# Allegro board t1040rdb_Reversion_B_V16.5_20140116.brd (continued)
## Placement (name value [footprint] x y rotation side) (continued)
U26  PI3PCIE3212  [QFN_P050_D040_B450X250_20_E3X1]  234.7 97.54 0 top
U27  PI3PCIE3212  [QFN_P050_D040_B450X250_20_E3X1]  209.3 82.3 270 top
U28  PI3PCIE3212  [QFN_P050_D040_B450X250_20_E3X1]  234.7 106.43 0 top
U29  PI3PCIE3212  [QFN_P050_D040_B450X250_20_E3X1]  234.7 115.32 0 top
U37  MIC2506YM  [SO_8]  60.71 28.7 270 top
U38  VBUS054B-HSF  [TVS_LLP75_6L]  73.79 26.8 270 top
U39  MAX3232  [TSSOP_16]  136.14 66.42 90 top
U40  TXBN0304RSV  [QFN_P040_D040_B260X180_16]  171.2 92.46 270 top
U41  MAX3232  [TSSOP_16]  129.03 66.42 90 top
U42  TXBN0304RSV  [QFN_P040_D040_B260X180_16]  166.62 92.46 270 top
U43  LCDA15C-8  [SO_16]  131.19 33.4 0 top
U44  AT24C256  [SO_8]  236.47 150.5 0 top
U45  ADT7461  [MSOP_8]  144.91 120.52 180 bottom
U46  RTL8211E-VB  [QFN_P040_D040_B600_48_E440]  158.5 49.91 90 top
U47  SRV05-4  [SOT23_6]  155.96 42.29 270 top
U48  SRV05-4  [SOT23_6]  162.05 42.29 270 top
U49  RTL8211E-VB  [QFN_P040_D040_B600_48_E440]  136.27 50.55 90 top
U50  SRV05-4  [SOT23_6]  139.57 42.29 270 top
U51  SRV05-4  [SOT23_6]  145.54 42.29 270 top
U52  RTL8211DN  [QFN_P040_D040_B1000_88_E600]  191.52 65.15 90 top
U53  SRV05-4  [SOT23_6]  190.12 30.23 270 top
U54  SRV05-4  [SOT23_6]  196.09 30.23 270 top
U55  F104S8A  [QFN_VSC8514]  212.47 65.15 180 top
U56  F104S8A  [QFN_VSC8514]  246.76 65.15 180 top
U57  CS4315  [BGA_P100_121]  169.29 65.15 0 top
U58  AT24C64  [TSSOP_8]  159.77 62.99 90 top
U59  Le88266DLC  [QFP_P065_80_E780]  86.74 56.9 180 top
U60  TISP61089B  [SO_8]  93.6 41.78 270 top
U61  TISP61089B  [SO_8]  84.71 41.78 270 top
U62  TISP61089B  [SO_8]  111.38 41.78 270 top
U63  Le88266DLC  [QFP_P065_80_E780]  109.6 56.9 180 top
U64  TISP61089B  [SO_8]  102.49 41.78 270 top
U65  EPM570GF256  [BGA_P100_256]  64.52 106.43 0 top
U67  ICS843002-01  [TSSOP_20]  231.27 72.39 0 top
U68  ICS843002-01  [TSSOP_20]  152.27 67.18 0 top
U69  IR3550  [QFN_IR3550]  107.82 94.23 90 top
U70  IR36021  [QFN_P050_D040_B500_32_E345]  100.71 83.57 90 bottom
U71  IR3550  [QFN_IR3550]  107.82 104.39 90 top
U72  MIC39102YM  [SO_8]  93.22 82.3 0 top
U81  TPS51200  [DFN_P050_D040_B300_10_E240X165]  227.33 146.69 270 top
U82  NCP571  [SOT23_5]  72.64 151.13 180 top
U83  MIC811  [SOT143]  19.05 65.41 180 top
U84  74LVC2G74  [U8]  11.18 64.01 180 top
U85  74AHC1G14  [SC70_5]  12.32 61.21 90 top
U86  IR3473  [QFN_SUPIRBUCK_4X5]  197.23 79.76 90 top
U87  IR3475  [QFN_SUPIRBUCK_4X5]  217.55 136.91 90 top
U88  IR3473  [QFN_SUPIRBUCK_4X5]  23.88 112.14 270 top
U89  IR3473  [QFN_SUPIRBUCK_4X5]  23.88 101.35 270 top
U90  IR3475  [QFN_SUPIRBUCK_4X5]  23.88 90.55 270 top
U91  IR3473  [QFN_SUPIRBUCK_4X5]  61.34 80.39 270 top
U92  ADG836  [MSOP_10]  107.19 78.61 180 bottom
U93  RClamp0524J.TCT  [TVS_SLP2710P8]  44.45 37.34 180 bottom
U94  RClamp0524J.TCT  [TVS_SLP2710P8]  30.73 37.34 180 bottom
U95  MIC47100YMME  [MSOP_8_E170]  207.9 125.98 180 top
U96  VBUS054B-HSF  [TVS_LLP75_6L]  76.33 26.8 270 top
U97  IDT9FGV0641  [QFN_P040_D040_B500_40_E370]  236.6 136.91 90 top
U98  TXBN0304RSV  [QFN_P040_D040_B260X180_16]  81.41 130.68 180 bottom
U99  TXBN0304RSV  [QFN_P040_D040_B260X180_16]  81.41 124.59 180 bottom
U100  74LVC1G32  [SC70_5]  272.42 140.72 0 top
U101  74LVC1G32  [SC70_5]  275.21 140.72 0 top
X1  24MHz,+/-50ppm  [OSC_7X5_4]  84.84 89.28 0 top
X2  32.768KHz  [OSC_32X25_4]  51.69 111.38 0 top
X3  100MHz,+/-50ppm  [OSC_7X5_4]  84.84 97.54 0 top
X5  66.66MHz,+/-50ppm  [OSC_7X5_4]  84.84 105.79 0 top
Y1  25MHz  [CRY_32X25_4]  150.5 50.8 270 top
Y2  25MHz  [CRY_32X25_4]  128.27 51.43 270 top
Y3  25MHz  [CRY_32X25_4]  182.25 62.74 270 top
Y4  25MHz  [CRY_32X25_4]  235.46 130.17 0 top
Y5  25MHz  [CRY_32X25_4]  155.07 60.45 0 top
Y6  25MHz  [CRY_32X25_4]  232.28 65.53 0 top
Z97  -  [FIDUCIAL]  274.7 18.16 0 top
Z98  -  [FIDUCIAL]  11.81 239.14 0 top
Z99  -  [FIDUCIAL]  10.54 22.61 0 top
Z100  -  [FIDUCIAL]  268.99 240.41 0 top
Z101  -  [FIDUCIAL]  274.7 18.16 180 bottom
Z102  -  [FIDUCIAL]  11.81 239.14 180 bottom
Z103  -  [FIDUCIAL]  268.99 240.41 180 bottom
Z104  -  [FIDUCIAL]  10.54 22.61 180 bottom
Z105  MH_M8  [MH_900C400N_M]  141.02 245.02 0 top
Z106  MH_M8  [MH_900C400N_M]  275.02 245.02 0 top
Z107  MH_M8  [MH_900C400N_M]  127.02 11.02 0 top
Z108  MH_M8  [MH_900C400N_M]  275.02 11.02 0 top
Z109  MH_M8  [MH_900C400N_M]  7.02 16.02 0 top
Z110  MH_M8  [MH_900C400N_M]  7.02 245.02 0 top
Z111  MH_M8  [MH_900C400N_M]  34.04 133.73 0 top
Z112  MH_M8  [MH_900C400N_M]  220.73 84.84 0 top

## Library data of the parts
C1 C2 C15 C375 C391 C576 C578 C580 C583 C592 C596 C755 C758 C773 C774 C781-C784 C787-C794 C885 C886 C925 C926 C930 C931 C952-C955 C975 C976 C979 C980 = CAP: signal model: DEFAULT_CAPACITOR_2.2e+07pF_2_1
C3-C14 C16-C21 C23-C26 C28-C32 C34 C35 C37 C39-C43 C48-C54 C57-C68 C84 C93 C94 C131 C133 C136 C147 C148 C150-C159 C170 C171 C176 C177 C179 C180 C182-C185 C192 C196-C208 C210-C220 C222 C232 C245-C248 C252-C256 C271-C275 C280-C288 C293 C295 C297 C306 C313-C317 C319-C323 C325 C326 C329 C336 C344 C346-C351 C353-C355 C357 C358 C361 C366-C368 C376-C378 C381-C386 C388-C390 C392 C393 C398-C400 C403-C407 C410 C411 C414-C416 C423-C425 C435-C437 C445 C448-C451 C454-C456 C459 C461 C462 C468-C470 C480-C482 C490-C497 C504-C511 C518-C525 C532-C539 C549 C554 C555 C564 C565 C572-C575 C586 C590 C593 C594 C597-C599 C602-C608 C611-C619 C622-C625 C627-C631 C636 C645 C649-C651 C653-C658 C669 C673-C675 C677-C681 C685 C686 C688 C694 C695 C699-C701 C704 C706-C710 C712-C716 C720 C723 C729 C732 C735 C742-C749 C762 C883 C891 C893-C898 C916-C919 C933 C935 C940 C941 C961 C963-C965 C984 C987-C989 C997-C1002 C1011 C1012 C1018-C1022 C1025-C1036 C1044-C1048 C1050-C1052 C1059-C1062 C1071-C1074 C1076 C1079 C1081-C1087 = CAP: signal model: DEFAULT_CAPACITOR_100000pF_2_1
C22 C69-C83 C85 C134 C139 C163-C169 C223-C230 C296 C298 C299 C301 C310 C328 C330 C332 C333 C342 C360 C362-C364 C371 C544 C545 C548 C550 C552 C553 C591 C595 C632-C635 C702 C721 C730 C737 C751 C753 C761 C770 C871 C873-C876 C878 C879 C920-C923 C932 C938 C945 C947 C956 C957 C969 C971 C977 C981 C993 C995 C996 C1003-C1010 C1023 C1024 C1037-C1039 C1041 C1078 = CAP: signal model: DEFAULT_CAPACITOR_10000pF_2_1
C27 C33 C36 C38 C135 C238-C241 C258 C263 C268 C270 C402 C413 C422 C434 C440 C447 C458 C467 C479 C485 C558-C563 C568-C571 C577 C579 C581 C582 C584 C585 C587-C589 C693 C698 C703 C705 C711 C722 C731 C760 C796 C884 C899-C903 C912-C915 C928 C929 C944 C946 C950 C951 C968 C970 C972-C974 C978 C992 C994 C1015 C1016 C1053-C1058 C1088-C1094 = CAP: signal model: DEFAULT_CAPACITOR_1e+06pF_2_1
C55 C56 C132 C300 C303 C331 C335 C718 C728 = CAP: signal model: DEFAULT_CAPACITOR_10.000000pF_2_1
C92 C125 C128 C130 C137 C140-C146 C175 C178 C181 C186-C189 C195 C209 C234-C237 C257 C262 C267 C269 C401 C412 C420 C421 C432 C433 C446 C457 C465 C466 C477 C478 C556 C557 C566 C567 C600 C601 C609 C610 C621 C626 C646 C670 C736 C750 C752 C754 C757 C771 C772 C797 C880 C881 C888-C890 C904-C911 C1017 C1040 C1049 C1075 C1077 = CAP: signal model: DEFAULT_CAPACITOR_1e+07pF_2_1
C124 C127 C620 C689 = CAP_E: signal model: DEFAULT_CAPACITOR_1e+08pF_2_1
C126 C129 C294 C302 C309 C334 C341 C365 C374 C498 C499 C512 C513 C526 C527 C541 C542 C690 C766 C786 C887 = CAP: signal model: DEFAULT_CAPACITOR_1000pF_2_1
C138 C149 C161 C162 C173 C174 C242 C243 C249 C250 C798 = CAP: signal model: DEFAULT_CAPACITOR_2.2e+06pF_2_1
C160 C172 C244 C251 C259 C264 C764 = CAP: signal model: DEFAULT_CAPACITOR_3000pF_2_1
C260 C265 C312 C324 C343 C356 C551 C647 C648 C652 C671 C672 C676 C795 C882 = CAP: signal model: DEFAULT_CAPACITOR_4.7e+06pF_2_1
C261 C266 C934 C936 C937 C939 C958-C960 C962 C982 C983 C985 C986 C1063 C1064 C1066-C1070 C1095-C1100 = CAP: signal model: DEFAULT_CAPACITOR_4.7e+07pF_2_1
C276-C279 C289-C292 C778 = CAP: signal model: DEFAULT_CAPACITOR_100.000000pF_2_1
C304 C305 C339 C340 C372 C373 C739 C740 = CAP: signal model: DEFAULT_CAPACITOR_27.000000pF_2_1
C307 C308 C337 C338 C369 C370 C500-C503 C514-C517 C528-C531 C540 C543 C546 C547 C696 = CAP: signal model: DEFAULT_CAPACITOR_470.000000pF_2_1
C637 C638 C642 C644 C659 C660 C666 C668 = CAP: signal model: DEFAULT_CAPACITOR_68000pF_2_1
C639-C641 C643 C661 C662 C664 C667 = CAP: signal model: DEFAULT_CAPACITOR_22000pF_2_1
C682 = CAP: signal model: DEFAULT_CAPACITOR_4700pF_2_1
C683 = CAP: signal model: DEFAULT_CAPACITOR_4.700000pF_2_1
C684 = CAP: signal model: DEFAULT_CAPACITOR_330.000000pF_2_1
C687 C767 C768 C776 C777 = CAP_E: signal model: DEFAULT_CAPACITOR_4.7e+08pF_2_1
C691 C692 = CAP_E: signal model: DEFAULT_CAPACITOR_8.2e+07pF_2_1
C697 = CAP: signal model: DEFAULT_CAPACITOR_220.000000pF_2_1
C733 C734 = CAP: signal model: DEFAULT_CAPACITOR_2.000000pF_2_1
C738 C741 = CAP: signal model: DEFAULT_CAPACITOR_33.000000pF_2_1
C756 C763 C765 C769 C779 C785 = CAP: signal model: DEFAULT_CAPACITOR_220000pF_2_1
C759 C775 C1080 = CAP_E: signal model: DEFAULT_CAPACITOR_2.2e+08pF_2_1
C892 = CAP: signal model: DEFAULT_CAPACITOR_22.000000pF_2_1
C924 = CAP: signal model: DEFAULT_CAPACITOR_330000pF_2_1
C927 C948 C949 = CAP: signal model: DEFAULT_CAPACITOR_470000pF_2_1
C942 = CAP: signal model: DEFAULT_CAPACITOR_510.000000pF_2_1
C943 C966 = CAP: signal model: DEFAULT_CAPACITOR_560.000000pF_2_1
C967 = CAP: signal model: DEFAULT_CAPACITOR_620.000000pF_2_1
C990 C991 = CAP: signal model: DEFAULT_CAPACITOR_680.000000pF_2_1
C1013 C1014 = CAP_3T_4P
C1101-C1113 = CAP
D1 D5 D6 D36-D44 = LED
D3 D4 D25 D26 D28 = DIODE
D22 D30 D31 D33-D35 = DIODE_SCHOTTKY
D27 = DIODE_DUAL_A
F1-F13 = PTC
FB6-FB13 FB18-FB26 FB29 FB32 FB35-FB48 FB50 FB52-FB55 = BEAD
J1 = DDR3_DIMM
J2 = SD_CONN
J3 = CONN_2X8
J9-J11 J27 = JMP2
J13 = RJ45_2X1
J14 = RJ45_LED_2X1
J15 = RJ45_LED_8
J16 = SFP+_CONN
J17 = SFP_CAGE
J18 = PCIE_X4
J19 J20 = MINIPCIE_CONN
J21 = SATA_CONN
J22 J23 = RJ11_6P_2
J24 = RJ11_4P
J25 = TQ2-3V
J26 = CONN_2X5
J28 J32 = CONN_1X3
J30 = BAT_SOCKET
J31 J35 J39 = CONN_1X2
J33 J34 J44-J46 = CONN_3PIN
J37 = ATX_PWR_CONN_20PIN
J41 = USB_A_2
J42 = RJ45_LED
J43 = CONN_2X20
L1 L2 = IND_CM
L3 L4 L17 L18 L22 = IND_IRON: signal model: DEFAULT_INDUCTOR_2200nH_2_1
L5 L21 = IND_IRON: signal model: DEFAULT_INDUCTOR_4700nH_2_1
L6 = IND_IRON: signal model: DEFAULT_INDUCTOR_220000nH_2_1
L7 = IND_IRON: signal model: DEFAULT_INDUCTOR_100000nH_2_1
L8 L9 = IND_IRON: signal model: DEFAULT_INDUCTOR_215.000000nH_2_1
L16 = IND_IRON: signal model: DEFAULT_INDUCTOR_22000nH_2_1
L19 L20 = IND_IRON: signal model: DEFAULT_INDUCTOR_3300nH_2_1
L23 = IND_IRON: signal model: DEFAULT_INDUCTOR_1000nH_2_1
M2 = HEATSINK_FAN
M3-M18 = MH
Q1-Q4 Q6 Q7 Q13 Q15 Q16 Q20 Q21 Q25-Q29 Q32-Q41 Q44 Q45 = NMOS
Q5 = TRANS_PNP
Q8 Q9 Q11 Q17 Q18 Q23 Q24 Q31 Q42 Q43 = NMOS_SO8FL
Q12 = PMOS_SO8
Q30 = TRANS_NPN
R1 R3 = RES: tolerance: 1%; signal model: DEFAULT_RESISTOR_162.000000OHM_2_1
R2 R48 R83 R84 R138 R161 R162 R174 R176 R302 R323 R488 R494 R503 R505 R507 R509 R513 R516 R518 R533 R540 R560 R568 R654 R656 R665 R666 R670 R672 R673 R681 R682 R687 R692 R713 R782 R785 R815 R820 R829 R830 R834 R842-R844 R860 = RES: tolerance: 5%; signal model: DEFAULT_RESISTOR_1000.000000OHM_2_1
R4-R7 R9-R11 R13 R17 R19 R21 R23 R25 R27 R29 R31 R33-R47 R54-R57 R69-R82 R85-R99 R101 R102 R123 R124 R132 R135-R137 R141-R143 R185 R204 R228-R235 R252 R257-R264 R268-R270 R272 R273 R276-R279 R282 R293-R297 R314-R317 R320 R379-R385 R387-R393 R396-R411 R420 R428 R442 R496 R499-R501 R563 R569 R570 R573 R574 R705 R706 R708 R710 R712 R808-R813 R823 R845-R859 = RES: tolerance: 5%; signal model: DEFAULT_RESISTOR_4700OHM_2_1
R12 R59 R100 R108 R115-R122 R125-R130 R468 R486 R490 R549 R550 R553 R555 R694 R839 R841 = RES: tolerance: 5%; signal model: DEFAULT_RESISTOR_10.000000OHM_2_1
R14-R16 R18 R20 R22 R24 R26 R28 R30 R32 R58 R175 R209 R211 R213-R217 R238 R239 R242-R246 R419 R422 R448 R449 R495 R511 R517 = RES: tolerance: 5%; signal model: DEFAULT_RESISTOR_33.000000OHM_2_1
R49-R52 R61 R157 R160 R167-R170 R180 R182-R184 R190 R193 R221 R222 R250 R251 R281 R291 R312 R489 R520 R521 R525 R526 R530 R532 R536 R537 R552 R554 R559 R561 R579 R588 R589 R657 R659 R675 R676 R688 R689 R700 R701 R727 R742 R743 R760 R761 R778 R779 R783 R816 R817 R822 R824-R828 R836 R837 = RES: tolerance: 5%; signal model: DEFAULT_RESISTOR_0.001OHM_2_1
R60 R62-R68 R106 R107 R109-R114 R155 R156 R158 R159 R497 R498 R502 R504 R506 R508 R558 R564 R593 R660 R662 R663 R667 R669 R671 R678 R679 R684 R685 R690 R691 R693 R703 R704 R726 R732 R734 R737 R739-R741 R750 R752 R754 R756 R758 R759 R768 R770 R771 R773 R776 R777 R784 R786 R818 R819 R821 R831 = RES: tolerance: 5%; signal model: DEFAULT_RESISTOR_10000OHM_2_1
R103 R133 R186 R187 R218 R219 R247 R248 R274 R275 R339-R342 R351-R354 R363-R366 R375-R378 R394 R395 R439 R440 R470-R472 R699 R702 = RES: tolerance: 5%; signal model: DEFAULT_RESISTOR_510.000000OHM_2_1
R104 R105 R140 = RES: tolerance: 1%; signal model: DEFAULT_RESISTOR_698.000000OHM_2_1
R131 = RES: tolerance: 5%; signal model: DEFAULT_RESISTOR_1500OHM_2_1
R134 = RES: tolerance: 5%; signal model: DEFAULT_RESISTOR_270.000000OHM_2_1
R139 = RES: tolerance: 1%; signal model: DEFAULT_RESISTOR_200.000000OHM_2_1
R163 R164 = RES: tolerance: 1%; signal model: DEFAULT_RESISTOR_51100OHM_2_1
R165 R166 = RES: tolerance: 1%; signal model: DEFAULT_RESISTOR_18200OHM_2_1
R171 R599 R729 R731 R736 R738 R744 R748 R749 R753 R757 R766 R767 R772 R774 R807 = RES: tolerance: 1%; signal model: DEFAULT_RESISTOR_10000OHM_2_1
R172 R173 R519 R523 R524 R527 R528 R534 R535 R538 R814 R835 R838 = RES: tolerance: 1%; signal model: DEFAULT_RESISTOR_49.900000OHM_2_1
R177-R179 = RES: tolerance: 5%; signal model: DEFAULT_RESISTOR_330.000000OHM_2_1
R188 R191 R194 R195 = RES: tolerance: 5%; signal model: DEFAULT_RESISTOR_5.100000OHM_2_1
R189 R192 = RES: tolerance: 1%; signal model: DEFAULT_RESISTOR_0.33OHM_2_1
R196-R203 R205 R206 R220 R249 R280 R292 R313 R386 R426 R455 R551 R556 R707 R711 = RES: tolerance: 5%; signal model: DEFAULT_RESISTOR_100.000000OHM_2_1
R207 R208 R210 R212 R236 R237 R240 R241 R265-R267 R271 R331-R338 R343-R350 R355-R362 R367-R374 R595 = RES: tolerance: 5%; signal model: DEFAULT_RESISTOR_75.000000OHM_2_1
R224 R284 = RES: tolerance: 5%; signal model: DEFAULT_RESISTOR_15.000000OHM_2_1
R227 R256 R285 R780 = RES: tolerance: 1%; signal model: DEFAULT_RESISTOR_2490OHM_2_1
R253 = RES: signal model: DEFAULT_RESISTOR_15.000000OHM_2_1
R286 = RES: tolerance: 1%; signal model: DEFAULT_RESISTOR_12100OHM_2_1
R303 R324 = RES: tolerance: 1%; signal model: DEFAULT_RESISTOR_2000OHM_2_1
R412 R413 R434 R435 R441 R451 R464 R465 R480 R481 R716-R723 = RES: tolerance: 5%; signal model: DEFAULT_RESISTOR_200000OHM_2_1
R414 R416 R429 R431 R444 R452 R459 R461 = RES: tolerance: 1%; signal model: DEFAULT_RESISTOR_3010OHM_2_1
R417 R418 R421 R423 R425 R445-R447 R450 R453 = RES: tolerance: 5%; signal model: DEFAULT_RESISTOR_51.000000OHM_2_1
R430 R433 R460 R463 R473-R479 = RES: tolerance: 1%; signal model: DEFAULT_RESISTOR_402000OHM_2_1
R436 R437 R466 R467 = RES: tolerance: 1%; signal model: DEFAULT_RESISTOR_47500OHM_2_1
R438 R469 = RES: tolerance: 1%; signal model: DEFAULT_RESISTOR_75000OHM_2_1
R482-R485 = RES: tolerance: 5%; signal model: DEFAULT_RESISTOR_1800OHM_2_1
R487 R493 R557 = RES: tolerance: 5%; signal model: DEFAULT_RESISTOR_13000OHM_2_1
R491 = RES: tolerance: 2%; signal model: DEFAULT_RESISTOR_0.02OHM_2_1
R541-R548 = RES: tolerance: 5%; signal model: DEFAULT_RESISTOR_150.000000OHM_2_1
R562 R586 = RES: tolerance: 1%; signal model: DEFAULT_RESISTOR_3570OHM_2_1
R565 R566 R581 R582 R590 R591 = RES: tolerance: 1%; signal model: DEFAULT_RESISTOR_301.000000OHM_2_1
R567 R592 = RES: tolerance: 5%; signal model: DEFAULT_RESISTOR_1.000000OHM_2_1
R575 R781 = RES: tolerance: 1%; signal model: DEFAULT_RESISTOR_1780OHM_2_1
R576 R580 = RES: tolerance: 1%; signal model: DEFAULT_RESISTOR_2870OHM_2_1
R577 = RES_NTC: signal model: DEFAULT_RESISTOR_10000OHM_2_1
R578 = RES: tolerance: 1%; signal model: DEFAULT_RESISTOR_3400OHM_2_1
R594 = RES: tolerance: 1%; signal model: DEFAULT_RESISTOR_7500OHM_2_1
R596 = RES: tolerance: 1%; signal model: DEFAULT_RESISTOR_20000OHM_2_1
R597 = RES: tolerance: 1%; signal model: DEFAULT_RESISTOR_49900OHM_2_1
R598 = RES: tolerance: 1%; signal model: DEFAULT_RESISTOR_46400OHM_2_1
R695 R696 = RES: tolerance: 1%; signal model: DEFAULT_RESISTOR_1000.000000OHM_2_1
R697 R714 R715 = RES: tolerance: 5%; signal model: DEFAULT_RESISTOR_100000OHM_2_1
R709 = RES: tolerance: 1%; signal model: DEFAULT_RESISTOR_3740OHM_2_1
R724 R725 = RES: tolerance: 1%; signal model: DEFAULT_RESISTOR_619.000000OHM_2_1
R728 = RES: tolerance: 1%; signal model: DEFAULT_RESISTOR_169000OHM_2_1
R730 = RES: tolerance: 1%; signal model: DEFAULT_RESISTOR_124000OHM_2_1
R733 = RES: tolerance: 1%; signal model: DEFAULT_RESISTOR_1650OHM_2_1
R735 = RES: tolerance: 1%; signal model: DEFAULT_RESISTOR_2050OHM_2_1
R745 = RES: tolerance: 1%; signal model: DEFAULT_RESISTOR_5900OHM_2_1
R746 = RES: tolerance: 1%; signal model: DEFAULT_RESISTOR_187000OHM_2_1
R747 = RES: tolerance: 1%; signal model: DEFAULT_RESISTOR_226000OHM_2_1
R751 = RES: tolerance: 1%; signal model: DEFAULT_RESISTOR_2210OHM_2_1
R755 = RES: tolerance: 1%; signal model: DEFAULT_RESISTOR_2430OHM_2_1
R762 = RES: tolerance: 1%; signal model: DEFAULT_RESISTOR_4990OHM_2_1
R763 = RES: tolerance: 1%; signal model: DEFAULT_RESISTOR_3830OHM_2_1
R764 = RES: tolerance: 1%; signal model: DEFAULT_RESISTOR_309000OHM_2_1
R765 = RES: tolerance: 1%; signal model: DEFAULT_RESISTOR_412000OHM_2_1
R769 = RES: tolerance: 1%; signal model: DEFAULT_RESISTOR_2550OHM_2_1
R775 = RES: tolerance: 1%; signal model: DEFAULT_RESISTOR_2320OHM_2_1
R787 = RES: tolerance: 1%; signal model: DEFAULT_RESISTOR_32400OHM_2_1
R797-R804 = RES: tolerance: 5%; signal model: DEFAULT_RESISTOR_20000OHM_2_1
R806 = RES: tolerance: 1%; signal model: DEFAULT_RESISTOR_4320OHM_2_1
R861-R870 = RES: tolerance: 5%
SW1-SW3 = SWITCH_DIP_8
SW4 SW5 = SWITCH_2P2
T1-T3 = H5004
T4-T11 = GST5009LF
T12 = XFMR_POTS_10PIN
TP1-TP14 = TP
U1 = T1040
U2 = 74LVC16373
U4 = FLASH-NOR-64Mx16
U6 = FLASH-NAND-2
U7 U11 U12 U18 U20 U40 U42 U98 U99 = TXBN0304RSV
U8-U10 = 74LVC1G86
U13 = FLASH-SERIAL-SO16
U15 = FLASH-SERIAL-SON
U19 = PCA9546A
U21 U22 = FXLP34P5X
U23 U24 = 74LVC1G66
U25-U29 = PI3PCIE3212
U37 = MIC2506
U38 U47 U48 U50 U51 U53 U54 U96 = SRV05-4
U39 U41 = MAX3232
U43 = LCDA15C-8
U44 U58 = EEPROM-I2C
U45 = ADT7461
U46 U49 = RTL8211E-VB
U52 = RTL8211DN
U55 U56 = VSC8514
U57 = CS4315
U59 U63 = Le88266DLC
U60-U62 U64 = TISP61089
U65 = EPM570F256
U67 U68 = ICS843002-01
U69 U71 = IR3550
U70 = IR36021
U72 = MIC39102-SOIC
U81 = TPS51200
U82 = NCP571
U83 = MAX811S
U84 = 74LVC2G74
U85 = 74LVC1G14
U86-U91 = IR3475
U92 = ADG836
U93 U94 = RClamp0524J
U95 = MIC47100-MSOP8
U97 = IDT9FGV0641
U100 U101 = 74LVC1G32
X1-X3 X5 = OSC
Y1-Y6 = CRYSTAL_4PIN
Z97-Z104 = FIDUCIAL
Z105-Z112 = MH_M8

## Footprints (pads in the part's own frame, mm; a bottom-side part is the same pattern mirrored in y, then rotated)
0201
  rect 0.35x0.35 smd: 1(-0.3,0) 2(0.3,0)
0402
  rect 0.55x0.55 smd: 1(-0.5,0) 2(0.5,0)
0402O
  custom 0.138x0.138 smd: 1(-0.5,0) 2(0.5,0)
0603
  rect 0.9x0.9 smd: 1(-0.8,0) 2(0.8,0)
0805
  rect 1x1.4 smd: 1(-1,0) 2(1,0)
1206
  rect 1.25x1.6 smd: 1(-1.5,0) 2(1.5,0)
1210
  rect 1.4x2.6 smd: 1(-1.6,0) 2(1.6,0)
7343
  rect 2.4x2.9 smd: 1(-3.05,0) 2(3.05,0)
BGA_P080_780
  round 0.35 smd: A2(-10,10.8) A3(-9.2,10.8) A4(-8.4,10.8) A5(-7.6,10.8) A6(-6.8,10.8) A7(-6,10.8) A8(-5.2,10.8) A9(-4.4,10.8) A10(-3.6,10.8) A11(-2.8,10.8) A12(-2,10.8) A13(-1.2,10.8) A14(-0.4,10.8) A15(0.4,10.8) A16(1.2,10.8) A17(2,10.8) A18(2.8,10.8) A19(3.6,10.8) A20(4.4,10.8) A21(5.2,10.8) A22(6,10.8) A23(6.8,10.8) A24(7.6,10.8) A25(8.4,10.8) A26(9.2,10.8) A27(10,10.8) AA1(-10.8,-5.2) AA2(-10,-5.2) AA3(-9.2,-5.2) AA4(-8.4,-5.2) AA5(-7.6,-5.2) AA6(-6.8,-5.2) AA7(-6,-5.2) AA8(-5.2,-5.2) AA9(-4.4,-5.2) AA10(-3.6,-5.2) AA11(-2.8,-5.2) AA12(-2,-5.2) AA13(-1.2,-5.2) AA14(-0.4,-5.2) AA15(0.4,-5.2) AA16(1.2,-5.2) AA17(2,-5.2) AA18(2.8,-5.2) AA19(3.6,-5.2) AA20(4.4,-5.2) AA21(5.2,-5.2) AA22(6,-5.2) AA23(6.8,-5.2) AA24(7.6,-5.2) AA25(8.4,-5.2) AA26(9.2,-5.2) AA27(10,-5.2) AA28(10.8,-5.2) AB1(-10.8,-6) AB2(-10,-6) AB3(-9.2,-6) AB4(-8.4,-6) AB5(-7.6,-6) AB6(-6.8,-6) AB7(-6,-6) AB8(-5.2,-6) AB9(-4.4,-6) AB10(-3.6,-6) AB11(-2.8,-6) AB12(-2,-6) AB13(-1.2,-6) AB14(-0.4,-6) AB15(0.4,-6) AB16(1.2,-6) AB17(2,-6) AB18(2.8,-6) AB19(3.6,-6) AB20(4.4,-6) AB21(5.2,-6) AB22(6,-6) AB23(6.8,-6) AB24(7.6,-6) AB25(8.4,-6) AB26(9.2,-6) AB27(10,-6) AB28(10.8,-6) AC1(-10.8,-6.8) AC2(-10,-6.8) AC3(-9.2,-6.8) AC4(-8.4,-6.8) AC5(-7.6,-6.8) AC6(-6.8,-6.8) AC7(-6,-6.8) AC8(-5.2,-6.8) AC9(-4.4,-6.8) AC10(-3.6,-6.8) AC11(-2.8,-6.8) AC12(-2,-6.8) AC13(-1.2,-6.8) AC14(-0.4,-6.8) AC15(0.4,-6.8) AC16(1.2,-6.8) AC17(2,-6.8) AC18(2.8,-6.8) AC19(3.6,-6.8) AC20(4.4,-6.8) AC21(5.2,-6.8) AC22(6,-6.8) AC23(6.8,-6.8) AC24(7.6,-6.8) AC25(8.4,-6.8) AC26(9.2,-6.8) AC27(10,-6.8) AC28(10.8,-6.8) AD1(-10.8,-7.6) AD2(-10,-7.6) AD3(-9.2,-7.6) AD4(-8.4,-7.6) AD5(-7.6,-7.6) AD6(-6.8,-7.6) AD7(-6,-7.6) AD8(-5.2,-7.6) AD9(-4.4,-7.6) AD10(-3.6,-7.6) AD11(-2.8,-7.6) AD12(-2,-7.6) AD13(-1.2,-7.6) AD14(-0.4,-7.6) AD15(0.4,-7.6) AD16(1.2,-7.6) AD17(2,-7.6) AD18(2.8,-7.6) AD19(3.6,-7.6) AD20(4.4,-7.6) AD21(5.2,-7.6) AD22(6,-7.6) AD23(6.8,-7.6) AD24(7.6,-7.6) AD25(8.4,-7.6) AD26(9.2,-7.6) AD27(10,-7.6) AD28(10.8,-7.6) AE1(-10.8,-8.4) AE2(-10,-8.4) AE3(-9.2,-8.4) AE4(-8.4,-8.4) AE5(-7.6,-8.4) AE6(-6.8,-8.4) AE7(-6,-8.4) AE8(-5.2,-8.4) AE9(-4.4,-8.4) AE10(-3.6,-8.4) AE11(-2.8,-8.4) AE12(-2,-8.4) AE13(-1.2,-8.4) AE14(-0.4,-8.4) AE15(0.4,-8.4) AE16(1.2,-8.4) AE17(2,-8.4) AE18(2.8,-8.4) AE19(3.6,-8.4) AE20(4.4,-8.4) AE21(5.2,-8.4) AE22(6,-8.4) AE23(6.8,-8.4) AE24(7.6,-8.4) AE25(8.4,-8.4) AE26(9.2,-8.4) AE27(10,-8.4) AE28(10.8,-8.4) AF1(-10.8,-9.2) AF2(-10,-9.2) AF3(-9.2,-9.2) AF4(-8.4,-9.2) AF5(-7.6,-9.2) AF6(-6.8,-9.2) AF7(-6,-9.2) AF8(-5.2,-9.2) AF9(-4.4,-9.2) AF10(-3.6,-9.2) AF11(-2.8,-9.2) AF12(-2,-9.2) AF13(-1.2,-9.2) AF14(-0.4,-9.2) AF15(0.4,-9.2) AF16(1.2,-9.2) AF17(2,-9.2) AF18(2.8,-9.2) AF19(3.6,-9.2) AF20(4.4,-9.2) AF21(5.2,-9.2) AF22(6,-9.2) AF23(6.8,-9.2) AF24(7.6,-9.2) AF25(8.4,-9.2) AF26(9.2,-9.2) AF27(10,-9.2) AF28(10.8,-9.2) AG1(-10.8,-10) AG2(-10,-10) AG3(-9.2,-10) AG4(-8.4,-10) AG5(-7.6,-10) AG6(-6.8,-10) AG7(-6,-10) AG8(-5.2,-10) AG9(-4.4,-10) AG10(-3.6,-10) AG11(-2.8,-10) AG12(-2,-10) AG13(-1.2,-10) AG14(-0.4,-10) AG15(0.4,-10) AG16(1.2,-10) AG17(2,-10) AG18(2.8,-10) AG19(3.6,-10) AG20(4.4,-10) AG21(5.2,-10) AG22(6,-10) AG23(6.8,-10) AG24(7.6,-10) AG25(8.4,-10) AG26(9.2,-10) AG27(10,-10) AG28(10.8,-10) AH2(-10,-10.8) AH3(-9.2,-10.8) AH4(-8.4,-10.8) AH5(-7.6,-10.8) AH6(-6.8,-10.8) AH7(-6,-10.8) AH8(-5.2,-10.8) AH9(-4.4,-10.8) AH10(-3.6,-10.8) AH11(-2.8,-10.8) AH12(-2,-10.8) AH13(-1.2,-10.8) AH14(-0.4,-10.8) AH15(0.4,-10.8) AH16(1.2,-10.8) AH17(2,-10.8) AH18(2.8,-10.8) AH19(3.6,-10.8) AH20(4.4,-10.8) AH21(5.2,-10.8) AH22(6,-10.8) AH23(6.8,-10.8) AH24(7.6,-10.8) AH25(8.4,-10.8) AH26(9.2,-10.8) AH27(10,-10.8) B1(-10.8,10) B2(-10,10) B3(-9.2,10) B4(-8.4,10) B5(-7.6,10) B6(-6.8,10) B7(-6,10) B8(-5.2,10) B9(-4.4,10) B10(-3.6,10) B11(-2.8,10) B12(-2,10) B13(-1.2,10) B14(-0.4,10) B15(0.4,10) B16(1.2,10) B17(2,10) B18(2.8,10) B19(3.6,10) B20(4.4,10) B21(5.2,10) B22(6,10) B23(6.8,10) B24(7.6,10) B25(8.4,10) B26(9.2,10) B27(10,10) B28(10.8,10) C1(-10.8,9.2) C2(-10,9.2) C3(-9.2,9.2) C4(-8.4,9.2) C5(-7.6,9.2) C6(-6.8,9.2) C7(-6,9.2) C8(-5.2,9.2) C9(-4.4,9.2) C10(-3.6,9.2) C11(-2.8,9.2) C12(-2,9.2) C13(-1.2,9.2) C14(-0.4,9.2) C15(0.4,9.2) C16(1.2,9.2) C17(2,9.2) C18(2.8,9.2) C19(3.6,9.2) C20(4.4,9.2) C21(5.2,9.2) C22(6,9.2) C23(6.8,9.2) C24(7.6,9.2) C25(8.4,9.2) C26(9.2,9.2) C27(10,9.2) C28(10.8,9.2) D1(-10.8,8.4) D2(-10,8.4) D3(-9.2,8.4) D4(-8.4,8.4) D5(-7.6,8.4) D6(-6.8,8.4) D7(-6,8.4) D8(-5.2,8.4) D9(-4.4,8.4) D10(-3.6,8.4) D11(-2.8,8.4) D12(-2,8.4) D13(-1.2,8.4) D14(-0.4,8.4) D15(0.4,8.4) D16(1.2,8.4) D17(2,8.4) D18(2.8,8.4) D19(3.6,8.4) D20(4.4,8.4) D21(5.2,8.4) D22(6,8.4) D23(6.8,8.4) D24(7.6,8.4) D25(8.4,8.4) D26(9.2,8.4) D27(10,8.4) D28(10.8,8.4) E1(-10.8,7.6) E2(-10,7.6) E3(-9.2,7.6) E4(-8.4,7.6) E5(-7.6,7.6) E6(-6.8,7.6) E7(-6,7.6) E8(-5.2,7.6) E9(-4.4,7.6) E10(-3.6,7.6) E11(-2.8,7.6) E12(-2,7.6) E13(-1.2,7.6) E14(-0.4,7.6) E15(0.4,7.6) E16(1.2,7.6) E17(2,7.6) E18(2.8,7.6) E19(3.6,7.6) E20(4.4,7.6) E21(5.2,7.6) E22(6,7.6) E23(6.8,7.6) E24(7.6,7.6) E25(8.4,7.6) E26(9.2,7.6) E27(10,7.6) E28(10.8,7.6) F1(-10.8,6.8) F2(-10,6.8) F3(-9.2,6.8) F4(-8.4,6.8) F5(-7.6,6.8) F6(-6.8,6.8) F7(-6,6.8) F8(-5.2,6.8) F9(-4.4,6.8) F10(-3.6,6.8) F11(-2.8,6.8) F12(-2,6.8) F13(-1.2,6.8) F14(-0.4,6.8) F15(0.4,6.8) F16(1.2,6.8) F17(2,6.8) F18(2.8,6.8) F19(3.6,6.8) F20(4.4,6.8) F21(5.2,6.8) F22(6,6.8) F23(6.8,6.8) F24(7.6,6.8) F25(8.4,6.8) F26(9.2,6.8) F27(10,6.8) F28(10.8,6.8) G1(-10.8,6) G2(-10,6) G3(-9.2,6) G4(-8.4,6) G5(-7.6,6) G6(-6.8,6) G7(-6,6) G8(-5.2,6) G9(-4.4,6) G10(-3.6,6) G11(-2.8,6) G12(-2,6) G13(-1.2,6) G14(-0.4,6) G15(0.4,6) G16(1.2,6) G17(2,6) G18(2.8,6) G19(3.6,6) G20(4.4,6) G21(5.2,6) G22(6,6) G23(6.8,6) G24(7.6,6) G25(8.4,6) G26(9.2,6) G27(10,6) G28(10.8,6) H1(-10.8,5.2) H2(-10,5.2) H3(-9.2,5.2) H4(-8.4,5.2) H5(-7.6,5.2) H6(-6.8,5.2) H7(-6,5.2) H8(-5.2,5.2) H9(-4.4,5.2) H10(-3.6,5.2) H11(-2.8,5.2) H12(-2,5.2) H13(-1.2,5.2) H14(-0.4,5.2) H15(0.4,5.2) H16(1.2,5.2) H17(2,5.2) H18(2.8,5.2) H19(3.6,5.2) H20(4.4,5.2) H21(5.2,5.2) H22(6,5.2) H23(6.8,5.2) H24(7.6,5.2) H25(8.4,5.2) H26(9.2,5.2) H27(10,5.2) H28(10.8,5.2) J1(-10.8,4.4) J2(-10,4.4) J3(-9.2,4.4) J4(-8.4,4.4) J5(-7.6,4.4) J6(-6.8,4.4) J7(-6,4.4) J8(-5.2,4.4) J9(-4.4,4.4) J10(-3.6,4.4) J11(-2.8,4.4) J12(-2,4.4) J13(-1.2,4.4) J14(-0.4,4.4) J15(0.4,4.4) J16(1.2,4.4) J17(2,4.4) J18(2.8,4.4) J19(3.6,4.4) J20(4.4,4.4) J21(5.2,4.4) J22(6,4.4) J23(6.8,4.4) J24(7.6,4.4) J25(8.4,4.4) J26(9.2,4.4) J27(10,4.4) J28(10.8,4.4) K1(-10.8,3.6) K2(-10,3.6) K3(-9.2,3.6) K4(-8.4,3.6) K5(-7.6,3.6) K6(-6.8,3.6) K7(-6,3.6) K8(-5.2,3.6) K9(-4.4,3.6) K10(-3.6,3.6) K11(-2.8,3.6) K12(-2,3.6) K13(-1.2,3.6) K14(-0.4,3.6) K15(0.4,3.6) K16(1.2,3.6) K17(2,3.6) K18(2.8,3.6) K19(3.6,3.6) K20(4.4,3.6) K21(5.2,3.6) K22(6,3.6) K23(6.8,3.6) K24(7.6,3.6) K25(8.4,3.6) K26(9.2,3.6) K27(10,3.6) K28(10.8,3.6) L1(-10.8,2.8) L2(-10,2.8) L3(-9.2,2.8) L4(-8.4,2.8) L5(-7.6,2.8) L6(-6.8,2.8) L7(-6,2.8) L8(-5.2,2.8) L9(-4.4,2.8) L10(-3.6,2.8) L11(-2.8,2.8) L12(-2,2.8) L13(-1.2,2.8) L14(-0.4,2.8) L15(0.4,2.8) L16(1.2,2.8) L17(2,2.8) L18(2.8,2.8) L19(3.6,2.8) L20(4.4,2.8) L21(5.2,2.8) L22(6,2.8) L23(6.8,2.8) L24(7.6,2.8) L25(8.4,2.8) L26(9.2,2.8) L27(10,2.8) L28(10.8,2.8) M1(-10.8,2) M2(-10,2) M3(-9.2,2) M4(-8.4,2) M5(-7.6,2) M6(-6.8,2) M7(-6,2) M8(-5.2,2) M9(-4.4,2) M10(-3.6,2) M11(-2.8,2) M12(-2,2) M13(-1.2,2) M14(-0.4,2) M15(0.4,2) M16(1.2,2) M17(2,2) M18(2.8,2) M19(3.6,2) M20(4.4,2) M21(5.2,2) M22(6,2) M23(6.8,2) M24(7.6,2) M25(8.4,2) M26(9.2,2) M27(10,2) M28(10.8,2) N1(-10.8,1.2) N2(-10,1.2) N3(-9.2,1.2) N4(-8.4,1.2) N5(-7.6,1.2) N6(-6.8,1.2) N7(-6,1.2) N8(-5.2,1.2) N9(-4.4,1.2) N10(-3.6,1.2) N11(-2.8,1.2) N12(-2,1.2) N13(-1.2,1.2) N14(-0.4,1.2) N15(0.4,1.2) N16(1.2,1.2) N17(2,1.2) N18(2.8,1.2) N19(3.6,1.2) N20(4.4,1.2) N21(5.2,1.2) N22(6,1.2) N23(6.8,1.2) N24(7.6,1.2) N25(8.4,1.2) N26(9.2,1.2) N27(10,1.2) N28(10.8,1.2) P1(-10.8,0.4) P2(-10,0.4) P3(-9.2,0.4) P4(-8.4,0.4) P5(-7.6,0.4) P6(-6.8,0.4) P7(-6,0.4) P8(-5.2,0.4) P9(-4.4,0.4) P10(-3.6,0.4) P11(-2.8,0.4) P12(-2,0.4) P13(-1.2,0.4) P14(-0.4,0.4) P15(0.4,0.4) P16(1.2,0.4) P17(2,0.4) P18(2.8,0.4) P19(3.6,0.4) P20(4.4,0.4) P21(5.2,0.4) P22(6,0.4) P23(6.8,0.4) P24(7.6,0.4) P25(8.4,0.4) P26(9.2,0.4) P27(10,0.4) P28(10.8,0.4) R1(-10.8,-0.4) R2(-10,-0.4) R3(-9.2,-0.4) R4(-8.4,-0.4) R5(-7.6,-0.4) R6(-6.8,-0.4) R7(-6,-0.4) R8(-5.2,-0.4) R9(-4.4,-0.4) R10(-3.6,-0.4) R11(-2.8,-0.4) R12(-2,-0.4) R13(-1.2,-0.4) R14(-0.4,-0.4) R15(0.4,-0.4) R16(1.2,-0.4) R17(2,-0.4) R18(2.8,-0.4) R19(3.6,-0.4) R20(4.4,-0.4) R21(5.2,-0.4) R22(6,-0.4) R23(6.8,-0.4) R24(7.6,-0.4) R25(8.4,-0.4) R26(9.2,-0.4) R27(10,-0.4) R28(10.8,-0.4) T1(-10.8,-1.2) T2(-10,-1.2) T3(-9.2,-1.2) T4(-8.4,-1.2) T5(-7.6,-1.2) T6(-6.8,-1.2) T7(-6,-1.2) T8(-5.2,-1.2) T9(-4.4,-1.2) T10(-3.6,-1.2) T11(-2.8,-1.2) T12(-2,-1.2) T13(-1.2,-1.2) T14(-0.4,-1.2) T15(0.4,-1.2) T16(1.2,-1.2) T17(2,-1.2) T18(2.8,-1.2) T19(3.6,-1.2) T20(4.4,-1.2) T21(5.2,-1.2) T22(6,-1.2) T23(6.8,-1.2) T24(7.6,-1.2) T25(8.4,-1.2) T26(9.2,-1.2) T27(10,-1.2) T28(10.8,-1.2) U1(-10.8,-2) U2(-10,-2) U3(-9.2,-2) U4(-8.4,-2) U5(-7.6,-2) U6(-6.8,-2) U7(-6,-2) U8(-5.2,-2) U9(-4.4,-2) U10(-3.6,-2) U11(-2.8,-2) U12(-2,-2) U13(-1.2,-2) U14(-0.4,-2) U15(0.4,-2) U16(1.2,-2) U17(2,-2) U18(2.8,-2) U19(3.6,-2) U20(4.4,-2) U21(5.2,-2) U22(6,-2) U23(6.8,-2) U24(7.6,-2) U25(8.4,-2) U26(9.2,-2) U27(10,-2) U28(10.8,-2) V1(-10.8,-2.8) V2(-10,-2.8) V3(-9.2,-2.8) V4(-8.4,-2.8) V5(-7.6,-2.8) V6(-6.8,-2.8) V7(-6,-2.8) V8(-5.2,-2.8) V9(-4.4,-2.8) V10(-3.6,-2.8) V11(-2.8,-2.8) V12(-2,-2.8) V13(-1.2,-2.8) V14(-0.4,-2.8) V15(0.4,-2.8) V16(1.2,-2.8) V17(2,-2.8) V18(2.8,-2.8) V19(3.6,-2.8) V20(4.4,-2.8) V21(5.2,-2.8) V22(6,-2.8) V23(6.8,-2.8) V24(7.6,-2.8) V25(8.4,-2.8) V26(9.2,-2.8) V27(10,-2.8) V28(10.8,-2.8) W1(-10.8,-3.6) W2(-10,-3.6) W3(-9.2,-3.6) W4(-8.4,-3.6) W5(-7.6,-3.6) W6(-6.8,-3.6) W7(-6,-3.6) W8(-5.2,-3.6) W9(-4.4,-3.6) W10(-3.6,-3.6) W11(-2.8,-3.6) W12(-2,-3.6) W13(-1.2,-3.6) W14(-0.4,-3.6) W15(0.4,-3.6) W16(1.2,-3.6) W17(2,-3.6) W18(2.8,-3.6) W19(3.6,-3.6) W20(4.4,-3.6) W21(5.2,-3.6) W22(6,-3.6) W23(6.8,-3.6) W24(7.6,-3.6) W25(8.4,-3.6) W26(9.2,-3.6) W27(10,-3.6) W28(10.8,-3.6) Y1(-10.8,-4.4) Y2(-10,-4.4) Y3(-9.2,-4.4) Y4(-8.4,-4.4) Y5(-7.6,-4.4) Y6(-6.8,-4.4) Y7(-6,-4.4) Y8(-5.2,-4.4) Y9(-4.4,-4.4) Y10(-3.6,-4.4) Y11(-2.8,-4.4) Y12(-2,-4.4) Y13(-1.2,-4.4) Y14(-0.4,-4.4) Y15(0.4,-4.4) Y16(1.2,-4.4) Y17(2,-4.4) Y18(2.8,-4.4) Y19(3.6,-4.4) Y20(4.4,-4.4) Y21(5.2,-4.4) Y22(6,-4.4) Y23(6.8,-4.4) Y24(7.6,-4.4) Y25(8.4,-4.4) Y26(9.2,-4.4) Y27(10,-4.4) Y28(10.8,-4.4)
BGA_P100_121
  round 0.4 smd: A1(-5,5) A2(-4,5) A3(-3,5) A4(-2,5) A5(-1,5) A6(0,5) A7(1,5) A8(2,5) A9(3,5) A10(4,5) A11(5,5) B1(-5,4) B2(-4,4) B3(-3,4) B4(-2,4) B5(-1,4) B6(0,4) B7(1,4) B8(2,4) B9(3,4) B10(4,4) B11(5,4) C1(-5,3) C2(-4,3) C3(-3,3) C4(-2,3) C5(-1,3) C6(0,3) C7(1,3) C8(2,3) C9(3,3) C10(4,3) C11(5,3) D1(-5,2) D2(-4,2) D3(-3,2) D4(-2,2) D5(-1,2) D6(0,2) D7(1,2) D8(2,2) D9(3,2) D10(4,2) D11(5,2) E1(-5,1) E2(-4,1) E3(-3,1) E4(-2,1) E5(-1,1) E6(0,1) E7(1,1) E8(2,1) E9(3,1) E10(4,1) E11(5,1) F1(-5,0) F2(-4,0) F3(-3,0) F4(-2,0) F5(-1,0) F6(0,0) F7(1,0) F8(2,0) F9(3,0) F10(4,0) F11(5,0) G1(-5,-1) G2(-4,-1) G3(-3,-1) G4(-2,-1) G5(-1,-1) G6(0,-1) G7(1,-1) G8(2,-1) G9(3,-1) G10(4,-1) G11(5,-1) H1(-5,-2) H2(-4,-2) H3(-3,-2) H4(-2,-2) H5(-1,-2) H6(0,-2) H7(1,-2) H8(2,-2) H9(3,-2) H10(4,-2) H11(5,-2) J1(-5,-3) J2(-4,-3) J3(-3,-3) J4(-2,-3) J5(-1,-3) J6(0,-3) J7(1,-3) J8(2,-3) J9(3,-3) J10(4,-3) J11(5,-3) K1(-5,-4) K2(-4,-4) K3(-3,-4) K4(-2,-4) K5(-1,-4) K6(0,-4) K7(1,-4) K8(2,-4) K9(3,-4) K10(4,-4) K11(5,-4) L1(-5,-5) L2(-4,-5) L3(-3,-5) L4(-2,-5) L5(-1,-5) L6(0,-5) L7(1,-5) L8(2,-5) L9(3,-5) L10(4,-5) L11(5,-5)
BGA_P100_256
  round 0.4 smd: A1(-7.5,7.5) A2(-6.5,7.5) A3(-5.5,7.5) A4(-4.5,7.5) A5(-3.5,7.5) A6(-2.5,7.5) A7(-1.5,7.5) A8(-0.5,7.5) A9(0.5,7.5) A10(1.5,7.5) A11(2.5,7.5) A12(3.5,7.5) A13(4.5,7.5) A14(5.5,7.5) A15(6.5,7.5) A16(7.5,7.5) B1(-7.5,6.5) B2(-6.5,6.5) B3(-5.5,6.5) B4(-4.5,6.5) B5(-3.5,6.5) B6(-2.5,6.5) B7(-1.5,6.5) B8(-0.5,6.5) B9(0.5,6.5) B10(1.5,6.5) B11(2.5,6.5) B12(3.5,6.5) B13(4.5,6.5) B14(5.5,6.5) B15(6.5,6.5) B16(7.5,6.5) C1(-7.5,5.5) C2(-6.5,5.5) C3(-5.5,5.5) C4(-4.5,5.5) C5(-3.5,5.5) C6(-2.5,5.5) C7(-1.5,5.5) C8(-0.5,5.5) C9(0.5,5.5) C10(1.5,5.5) C11(2.5,5.5) C12(3.5,5.5) C13(4.5,5.5) C14(5.5,5.5) C15(6.5,5.5) C16(7.5,5.5) D1(-7.5,4.5) D2(-6.5,4.5) D3(-5.5,4.5) D4(-4.5,4.5) D5(-3.5,4.5) D6(-2.5,4.5) D7(-1.5,4.5) D8(-0.5,4.5) D9(0.5,4.5) D10(1.5,4.5) D11(2.5,4.5) D12(3.5,4.5) D13(4.5,4.5) D14(5.5,4.5) D15(6.5,4.5) D16(7.5,4.5) E1(-7.5,3.5) E2(-6.5,3.5) E3(-5.5,3.5) E4(-4.5,3.5) E5(-3.5,3.5) E6(-2.5,3.5) E7(-1.5,3.5) E8(-0.5,3.5) E9(0.5,3.5) E10(1.5,3.5) E11(2.5,3.5) E12(3.5,3.5) E13(4.5,3.5) E14(5.5,3.5) E15(6.5,3.5) E16(7.5,3.5) F1(-7.5,2.5) F2(-6.5,2.5) F3(-5.5,2.5) F4(-4.5,2.5) F5(-3.5,2.5) F6(-2.5,2.5) F7(-1.5,2.5) F8(-0.5,2.5) F9(0.5,2.5) F10(1.5,2.5) F11(2.5,2.5) F12(3.5,2.5) F13(4.5,2.5) F14(5.5,2.5) F15(6.5,2.5) F16(7.5,2.5) G1(-7.5,1.5) G2(-6.5,1.5) G3(-5.5,1.5) G4(-4.5,1.5) G5(-3.5,1.5) G6(-2.5,1.5) G7(-1.5,1.5) G8(-0.5,1.5) G9(0.5,1.5) G10(1.5,1.5) G11(2.5,1.5) G12(3.5,1.5) G13(4.5,1.5) G14(5.5,1.5) G15(6.5,1.5) G16(7.5,1.5) H1(-7.5,0.5) H2(-6.5,0.5) H3(-5.5,0.5) H4(-4.5,0.5) H5(-3.5,0.5) H6(-2.5,0.5) H7(-1.5,0.5) H8(-0.5,0.5) H9(0.5,0.5) H10(1.5,0.5) H11(2.5,0.5) H12(3.5,0.5) H13(4.5,0.5) H14(5.5,0.5) H15(6.5,0.5) H16(7.5,0.5) J1(-7.5,-0.5) J2(-6.5,-0.5) J3(-5.5,-0.5) J4(-4.5,-0.5) J5(-3.5,-0.5) J6(-2.5,-0.5) J7(-1.5,-0.5) J8(-0.5,-0.5) J9(0.5,-0.5) J10(1.5,-0.5) J11(2.5,-0.5) J12(3.5,-0.5) J13(4.5,-0.5) J14(5.5,-0.5) J15(6.5,-0.5) J16(7.5,-0.5) K1(-7.5,-1.5) K2(-6.5,-1.5) K3(-5.5,-1.5) K4(-4.5,-1.5) K5(-3.5,-1.5) K6(-2.5,-1.5) K7(-1.5,-1.5) K8(-0.5,-1.5) K9(0.5,-1.5) K10(1.5,-1.5) K11(2.5,-1.5) K12(3.5,-1.5) K13(4.5,-1.5) K14(5.5,-1.5) K15(6.5,-1.5) K16(7.5,-1.5) L1(-7.5,-2.5) L2(-6.5,-2.5) L3(-5.5,-2.5) L4(-4.5,-2.5) L5(-3.5,-2.5) L6(-2.5,-2.5) L7(-1.5,-2.5) L8(-0.5,-2.5) L9(0.5,-2.5) L10(1.5,-2.5) L11(2.5,-2.5) L12(3.5,-2.5) L13(4.5,-2.5) L14(5.5,-2.5) L15(6.5,-2.5) L16(7.5,-2.5) M1(-7.5,-3.5) M2(-6.5,-3.5) M3(-5.5,-3.5) M4(-4.5,-3.5) M5(-3.5,-3.5) M6(-2.5,-3.5) M7(-1.5,-3.5) M8(-0.5,-3.5) M9(0.5,-3.5) M10(1.5,-3.5) M11(2.5,-3.5) M12(3.5,-3.5) M13(4.5,-3.5) M14(5.5,-3.5) M15(6.5,-3.5) M16(7.5,-3.5) N1(-7.5,-4.5) N2(-6.5,-4.5) N3(-5.5,-4.5) N4(-4.5,-4.5) N5(-3.5,-4.5) N6(-2.5,-4.5) N7(-1.5,-4.5) N8(-0.5,-4.5) N9(0.5,-4.5) N10(1.5,-4.5) N11(2.5,-4.5) N12(3.5,-4.5) N13(4.5,-4.5) N14(5.5,-4.5) N15(6.5,-4.5) N16(7.5,-4.5) P1(-7.5,-5.5) P2(-6.5,-5.5) P3(-5.5,-5.5) P4(-4.5,-5.5) P5(-3.5,-5.5) P6(-2.5,-5.5) P7(-1.5,-5.5) P8(-0.5,-5.5) P9(0.5,-5.5) P10(1.5,-5.5) P11(2.5,-5.5) P12(3.5,-5.5) P13(4.5,-5.5) P14(5.5,-5.5) P15(6.5,-5.5) P16(7.5,-5.5) R1(-7.5,-6.5) R2(-6.5,-6.5) R3(-5.5,-6.5) R4(-4.5,-6.5) R5(-3.5,-6.5) R6(-2.5,-6.5) R7(-1.5,-6.5) R8(-0.5,-6.5) R9(0.5,-6.5) R10(1.5,-6.5) R11(2.5,-6.5) R12(3.5,-6.5) R13(4.5,-6.5) R14(5.5,-6.5) R15(6.5,-6.5) R16(7.5,-6.5) T1(-7.5,-7.5) T2(-6.5,-7.5) T3(-5.5,-7.5) T4(-4.5,-7.5) T5(-3.5,-7.5) T6(-2.5,-7.5) T7(-1.5,-7.5) T8(-0.5,-7.5) T9(0.5,-7.5) T10(1.5,-7.5) T11(2.5,-7.5) T12(3.5,-7.5) T13(4.5,-7.5) T14(5.5,-7.5) T15(6.5,-7.5) T16(7.5,-7.5)
CAPE_B6D3
  rect 3.5x1.6 smd: 1(-2.8,0) 2(2.8,0)
CAPE_B8
  rect 4.15x1.9 smd: 1(-3.475,0) 2(3.475,0)
CAPE_P3D5_B8
  rect 1.4x1.4 hole 0.9: 1(-1.75,0)
  round 1.4 hole 0.9: 2(1.75,0)
CAPE_P5_B10
  rect 1.4x1.4 hole 0.9: 1(-2.5,0)
  round 1.4 hole 0.9: 2(2.5,0)
CAPE_P5_B12D5
  rect 1.4x1.4 hole 0.9: 1(-2.5,0)
  round 1.4 hole 0.9: 2(2.5,0)
CON_ATX_20PIN
  rect 1.9x1.9 hole 1.4: 1(-18.9,2.75)
  round 1.9 hole 1.4: 2(-14.7,2.75) 3(-10.5,2.75) 4(-6.3,2.75) 5(-2.1,2.75) 6(2.1,2.75) 7(6.3,2.75) 8(10.5,2.75) 9(14.7,2.75) 10(18.9,2.75) 11(-18.9,-2.75) 12(-14.7,-2.75) 13(-10.5,-2.75) 14(-6.3,-2.75) 15(-2.1,-2.75) 16(2.1,-2.75) 17(6.3,-2.75) 18(10.5,-2.75) 19(14.7,-2.75) 20(18.9,-2.75)
CON_BAT_WBA3B2
  round 1.5 hole 0.9: (-5,1.735) 2(0,-1.735)
  rect 1.5x1.5 hole 0.9: 1(5,1.735)
CON_DDR3_DIMM
  round 2.45 hole 2.45 unplated: (-57,0) (0,0) (81,0)
  round 1 hole 0.7: 1(-49.5,-0.95) 2(-48.5,-2.85) 3(-47.5,-0.95) 4(-46.5,-2.85) 5(-45.5,-0.95) 6(-44.5,-2.85) 7(-43.5,-0.95) 8(-42.5,-2.85) 9(-41.5,-0.95) 10(-40.5,-2.85) 11(-39.5,-0.95) 12(-38.5,-2.85) 13(-37.5,-0.95) 14(-36.5,-2.85) 15(-35.5,-0.95) 16(-34.5,-2.85) 17(-33.5,-0.95) 18(-32.5,-2.85) 19(-31.5,-0.95) 20(-30.5,-2.85) 21(-29.5,-0.95) 22(-28.5,-2.85) 23(-27.5,-0.95) 24(-26.5,-2.85) 25(-25.5,-0.95) 26(-24.5,-2.85) 27(-23.5,-0.95) 28(-22.5,-2.85) 29(-21.5,-0.95) 30(-20.5,-2.85) 31(-19.5,-0.95) 32(-18.5,-2.85) 33(-17.5,-0.95) 34(-16.5,-2.85) 35(-15.5,-0.95) 36(-14.5,-2.85) 37(-13.5,-0.95) 38(-12.5,-2.85) 39(-11.5,-0.95) 40(-10.5,-2.85) 41(-9.5,-0.95) 42(-8.5,-2.85) 43(-7.5,-0.95) 44(-6.5,-2.85) 45(-5.5,-0.95) 46(-4.5,-2.85) 47(-3.5,-0.95) 48(-2.5,-2.85) 49(2.5,-0.95) 50(3.5,-2.85) 51(4.5,-0.95) 52(5.5,-2.85) 53(6.5,-0.95) 54(7.5,-2.85) 55(8.5,-0.95) 56(9.5,-2.85) 57(10.5,-0.95) 58(11.5,-2.85) 59(12.5,-0.95) 60(13.5,-2.85) 61(14.5,-0.95) 62(15.5,-2.85) 63(16.5,-0.95) 64(17.5,-2.85) 65(18.5,-0.95) 66(19.5,-2.85) 67(20.5,-0.95) 68(21.5,-2.85) 69(22.5,-0.95) 70(23.5,-2.85) 71(24.5,-0.95) 72(25.5,-2.85) 73(26.5,-0.95) 74(27.5,-2.85) 75(28.5,-0.95) 76(29.5,-2.85) 77(30.5,-0.95) 78(31.5,-2.85) 79(32.5,-0.95) 80(33.5,-2.85) 81(34.5,-0.95) 82(35.5,-2.85) 83(36.5,-0.95) 84(37.5,-2.85) 85(38.5,-0.95) 86(39.5,-2.85) 87(40.5,-0.95) 88(41.5,-2.85) 89(42.5,-0.95) 90(43.5,-2.85) 91(44.5,-0.95) 92(45.5,-2.85) 93(46.5,-0.95) 94(47.5,-2.85) 95(48.5,-0.95) 96(49.5,-2.85) 97(50.5,-0.95) 98(51.5,-2.85) 99(52.5,-0.95) 100(53.5,-2.85) 101(54.5,-0.95) 102(55.5,-2.85) 103(56.5,-0.95) 104(57.5,-2.85) 105(58.5,-0.95) 106(59.5,-2.85) 107(60.5,-0.95) 108(61.5,-2.85) 109(62.5,-0.95) 110(63.5,-2.85) 111(64.5,-0.95) 112(65.5,-2.85) 113(66.5,-0.95) 114(67.5,-2.85) 115(68.5,-0.95) 116(69.5,-2.85) 117(70.5,-0.95) 118(71.5,-2.85) 119(72.5,-0.95) 120(73.5,-2.85) 121(-49.5,2.85) 122(-48.5,0.95) 123(-47.5,2.85) 124(-46.5,0.95) 125(-45.5,2.85) 126(-44.5,0.95) 127(-43.5,2.85) 128(-42.5,0.95) 129(-41.5,2.85) 130(-40.5,0.95) 131(-39.5,2.85) 132(-38.5,0.95) 133(-37.5,2.85) 134(-36.5,0.95) 135(-35.5,2.85) 136(-34.5,0.95) 137(-33.5,2.85) 138(-32.5,0.95) 139(-31.5,2.85) 140(-30.5,0.95) 141(-29.5,2.85) 142(-28.5,0.95) 143(-27.5,2.85) 144(-26.5,0.95) 145(-25.5,2.85) 146(-24.5,0.95) 147(-23.5,2.85) 148(-22.5,0.95) 149(-21.5,2.85) 150(-20.5,0.95) 151(-19.5,2.85) 152(-18.5,0.95) 153(-17.5,2.85) 154(-16.5,0.95) 155(-15.5,2.85) 156(-14.5,0.95) 157(-13.5,2.85) 158(-12.5,0.95) 159(-11.5,2.85) 160(-10.5,0.95) 161(-9.5,2.85) 162(-8.5,0.95) 163(-7.5,2.85) 164(-6.5,0.95) 165(-5.5,2.85) 166(-4.5,0.95) 167(-3.5,2.85) 168(-2.5,0.95) 169(2.5,2.85) 170(3.5,0.95) 171(4.5,2.85) 172(5.5,0.95) 173(6.5,2.85) 174(7.5,0.95) 175(8.5,2.85) 176(9.5,0.95) 177(10.5,2.85) 178(11.5,0.95) 179(12.5,2.85) 180(13.5,0.95) 181(14.5,2.85) 182(15.5,0.95) 183(16.5,2.85) 184(17.5,0.95) 185(18.5,2.85) 186(19.5,0.95) 187(20.5,2.85) 188(21.5,0.95) 189(22.5,2.85) 190(23.5,0.95) 191(24.5,2.85) 192(25.5,0.95) 193(26.5,2.85) 194(27.5,0.95) 195(28.5,2.85) 196(29.5,0.95) 197(30.5,2.85) 198(31.5,0.95) 199(32.5,2.85) 200(33.5,0.95) 201(34.5,2.85) 202(35.5,0.95) 203(36.5,2.85) 204(37.5,0.95) 205(38.5,2.85) 206(39.5,0.95) 207(40.5,2.85) 208(41.5,0.95) 209(42.5,2.85) 210(43.5,0.95) 211(44.5,2.85) 212(45.5,0.95) 213(46.5,2.85) 214(47.5,0.95) 215(48.5,2.85) 216(49.5,0.95) 217(50.5,2.85) 218(51.5,0.95) 219(52.5,2.85) 220(53.5,0.95) 221(54.5,2.85) 222(55.5,0.95) 223(56.5,2.85) 224(57.5,0.95) 225(58.5,2.85) 226(59.5,0.95) 227(60.5,2.85) 228(61.5,0.95) 229(62.5,2.85) 230(63.5,0.95) 231(64.5,2.85) 232(65.5,0.95) 233(66.5,2.85) 234(67.5,0.95) 235(68.5,2.85) 236(69.5,0.95) 237(70.5,2.85) 238(71.5,0.95) 239(72.5,2.85) 240(73.5,0.95)
CON_MEC6_120
  round 1.55 hole 1.55 unplated: (-1.5,7.535) (0,-7.535)
  rect 1.8x0.4 smd: 1(3.85,6.033) 2(-3.85,6.033) 3(3.85,5.398) 4(-3.85,5.398) 5(3.85,4.763) 6(-3.85,4.763) 7(3.85,4.128) 8(-3.85,4.128) 9(3.85,3.493) 10(-3.85,3.493) 11(3.85,2.858) 12(-3.85,2.858) 13(3.85,2.223) 14(-3.85,2.223) 15(3.85,1.588) 16(-3.85,1.588) 17(3.85,0.953) 18(-3.85,0.953) 19(3.85,0.318) 20(-3.85,0.318) 21(3.85,-0.317) 22(-3.85,-0.317) 23(3.85,-0.952) 24(-3.85,-0.952) 25(3.85,-1.587) 26(-3.85,-1.587) 27(3.85,-2.222) 28(-3.85,-2.222) 29(3.85,-2.857) 30(-3.85,-2.857) 31(3.85,-3.492) 32(-3.85,-3.492) 33(3.85,-4.127) 34(-3.85,-4.127) 35(3.85,-4.762) 36(-3.85,-4.762) 37(3.85,-5.397) 38(-3.85,-5.397) 39(3.85,-6.032) 40(-3.85,-6.032)
CON_MINIPCIE
  round 1.1 hole 1.1 unplated: (-12.5,0)
  round 1.6 hole 1.6 unplated: (12.5,0)
  rect 0.6x2 smd: 1(11.8,4.1) 2(11.4,-4.1) 3(11,4.1) 4(10.6,-4.1) 5(10.2,4.1) 6(9.8,-4.1) 7(9.4,4.1) 8(9,-4.1) 9(8.6,4.1) 10(8.2,-4.1) 11(7.8,4.1) 12(7.4,-4.1) 13(7,4.1) 14(6.6,-4.1) 15(6.2,4.1) 16(5.8,-4.1) 17(2.2,4.1) 18(1.8,-4.1) 19(1.4,4.1) 20(1,-4.1) 21(0.6,4.1) 22(0.2,-4.1) 23(-0.2,4.1) 24(-0.6,-4.1) 25(-1,4.1) 26(-1.4,-4.1) 27(-1.8,4.1) 28(-2.2,-4.1) 29(-2.6,4.1) 30(-3,-4.1) 31(-3.4,4.1) 32(-3.8,-4.1) 33(-4.2,4.1) 34(-4.6,-4.1) 35(-5,4.1) 36(-5.4,-4.1) 37(-5.8,4.1) 38(-6.2,-4.1) 39(-6.6,4.1) 40(-7,-4.1) 41(-7.4,4.1) 42(-7.8,-4.1) 43(-8.2,4.1) 44(-8.6,-4.1) 45(-9,4.1) 46(-9.4,-4.1) 47(-9.8,4.1) 48(-10.2,-4.1) 49(-10.6,4.1) 50(-11,-4.1) 51(-11.4,4.1) 52(-11.8,-4.1)
  rect 2.3x3.2 smd: 53(14.65,3.5) 54(-14.65,3.5)
CON_PEX4
  round 2.35 hole 2.35 unplated: (0,0) (23.15,0)
  rect 1.1x1.1 hole 0.7: A1(-11.65,1.25)
  round 1.1 hole 0.7: A2(-10.65,3.25) A3(-9.65,1.25) A4(-8.65,3.25) A5(-7.65,1.25) A6(-6.65,3.25) A7(-5.65,1.25) A8(-4.65,3.25) A9(-3.65,1.25) A10(-2.65,3.25) A11(-1.65,1.25) A12(1.35,3.25) A13(2.35,1.25) A14(3.35,3.25) A15(4.35,1.25) A16(5.35,3.25) A17(6.35,1.25) A18(7.35,3.25) A19(8.35,1.25) A20(9.35,3.25) A21(10.35,1.25) A22(11.35,3.25) A23(12.35,1.25) A24(13.35,3.25) A25(14.35,1.25) A26(15.35,3.25) A27(16.35,1.25) A28(17.35,3.25) A29(18.35,1.25) A30(19.35,3.25) A31(20.35,1.25) A32(21.35,3.25) B1(-11.65,-1.25) B2(-10.65,-3.25) B3(-9.65,-1.25) B4(-8.65,-3.25) B5(-7.65,-1.25) B6(-6.65,-3.25) B7(-5.65,-1.25) B8(-4.65,-3.25) B9(-3.65,-1.25) B10(-2.65,-3.25) B11(-1.65,-1.25) B12(1.35,-3.25) B13(2.35,-1.25) B14(3.35,-3.25) B15(4.35,-1.25) B16(5.35,-3.25) B17(6.35,-1.25) B18(7.35,-3.25) B19(8.35,-1.25) B20(9.35,-3.25) B21(10.35,-1.25) B22(11.35,-3.25) B23(12.35,-1.25) B24(13.35,-3.25) B25(14.35,-1.25) B26(15.35,-3.25) B27(16.35,-1.25) B28(17.35,-3.25) B29(18.35,-1.25) B30(19.35,-3.25) B31(20.35,-1.25) B32(21.35,-3.25)
CON_RJ11_4P_1X1
  round 3.2 hole 3.2 unplated: (-5.15,5.4) (5.15,5.4)
  round 1.27 hole 0.89: 1(1.53,11.3) 2(0.51,8.76) 3(-0.51,11.3) 4(-1.53,8.76)
CON_RJ11_6P_2X1
  round 3.2 hole 3.2 unplated: (-5.08,10.5) (5.08,10.5)
  round 1.4 hole 0.9: A1(3.175,23.45) A2(1.905,25.99) A3(0.635,23.45) A4(-0.635,25.99) A5(-1.905,23.45) A6(-3.175,25.99) B1(-3.175,19.39) B2(-1.905,16.85) B3(-0.635,19.39) B4(0.635,16.85) B5(1.905,19.39) B6(3.175,16.85)
CON_RJ45_2X1
  round 3.2 hole 3.2 unplated: (-5.715,10.8) (5.715,10.8)
  round 2.2 hole 1.6: 17(-8.505,26.29) 18(8.505,22.23) 19(-7.745,19.94) 20(7.745,16.64) 21(-8.505,6.23) 22(8.505,6.23)
  round 1.4 hole 0.9: A1(4.445,26.31) A2(3.175,23.77) A3(1.905,26.31) A4(0.635,23.77) A5(-0.635,26.31) A6(-1.905,23.77) A7(-3.175,26.31) A8(-4.445,23.77) B1(-4.445,17.15) B2(-3.175,19.69) B3(-1.905,17.15) B4(-0.635,19.69) B5(0.635,17.15) B6(1.905,19.69) B7(3.175,17.15) B8(4.445,19.69)
CON_RJ45_2X1_LED
  round 3.2 hole 3.2 unplated: (-6.35,5.46) (6.35,5.46)
  round 2.2 hole 1.6: 25(-8.13,12.57) 26(8.13,12.57) 27(-8.13,20.95) 28(8.13,20.95)
  round 1.4 hole 0.9: A1(4.445,22.48) A2(3.175,19.94) A3(1.905,22.48) A4(0.635,19.94) A5(-0.635,22.48) A6(-1.905,19.94) A7(-3.175,22.48) A8(-4.445,19.94) B1(-4.445,13.71) B2(-3.175,16.25) B3(-1.905,13.71) B4(-0.635,16.25) B5(0.635,13.71) B6(1.905,16.25) B7(3.175,13.71) B8(4.445,16.25)
  round 1.6 hole 1.1: A9(-6.86,26.41) A10(-4.32,26.41) A11(4.32,26.41) A12(6.86,26.41) B9(-6.86,9.65) B10(-4.32,9.65) B11(4.32,9.65) B12(6.86,9.65)
CON_RJ45_2X4_LED
  round 3.2 hole 3.2 unplated: (-29.975,5.46) (29.975,5.46)
  round 2.2 hole 1.6: 97(-31.755,12.57) 98(31.755,12.57) 99(-31.755,20.95) 100(31.755,20.95)
  round 1.4 hole 0.9: A1(-19.18,22.48) A2(-20.45,19.94) A3(-21.72,22.48) A4(-22.99,19.94) A5(-24.26,22.48) A6(-25.53,19.94) A7(-26.8,22.48) A8(-28.07,19.94) B1(-28.07,13.71) B2(-26.8,16.25) B3(-25.53,13.71) B4(-24.26,16.25) B5(-22.99,13.71) B6(-21.72,16.25) B7(-20.45,13.71) B8(-19.18,16.25) C1(-3.43,22.48) C2(-4.7,19.94) C3(-5.97,22.48) C4(-7.24,19.94) C5(-8.51,22.48) C6(-9.78,19.94) C7(-11.05,22.48) C8(-12.32,19.94) D1(-12.32,13.71) D2(-11.05,16.25) D3(-9.78,13.71) D4(-8.51,16.25) D5(-7.24,13.71) D6(-5.97,16.25) D7(-4.7,13.71) D8(-3.43,16.25) E1(12.32,22.48) E2(11.05,19.94) E3(9.78,22.48) E4(8.51,19.94) E5(7.24,22.48) E6(5.97,19.94) E7(4.7,22.48) E8(3.43,19.94) F1(3.43,13.71) F2(4.7,16.25) F3(5.97,13.71) F4(7.24,16.25) F5(8.51,13.71) F6(9.78,16.25) F7(11.05,13.71) F8(12.32,16.25) G1(28.07,22.48) G2(26.8,19.94) G3(25.53,22.48) G4(24.26,19.94) G5(22.99,22.48) G6(21.72,19.94) G7(20.45,22.48) G8(19.18,19.94) H1(19.18,13.71) H2(20.45,16.25) H3(21.72,13.71) H4(22.99,16.25) H5(24.26,13.71) H6(25.53,16.25) H7(26.8,13.71) H8(28.07,16.25)
  round 1.6 hole 1.1: A9(-30.485,26.41) A10(-27.945,26.41) A11(-19.305,26.41) A12(-16.765,26.41) B9(-30.485,9.65) B10(-27.945,9.65) B11(-19.305,9.65) B12(-16.765,9.65) C9(-14.735,26.41) C10(-12.195,26.41) C11(-3.555,26.41) C12(-1.015,26.41) D9(-14.735,9.65) D10(-12.195,9.65) D11(-3.555,9.65) D12(-1.015,9.65) E9(1.015,26.41) E10(3.555,26.41) E11(12.195,26.41) E12(14.735,26.41) F9(1.015,9.65) F10(3.555,9.65) F11(12.195,9.65) F12(14.735,9.65) G9(16.765,26.41) G10(19.305,26.41) G11(27.945,26.41) G12(30.485,26.41) H9(16.765,9.65) H10(19.305,9.65) H11(27.945,9.65) H12(30.485,9.65)
CON_RJ45_UP_1X1_LED
  round 3.25 hole 3.25 unplated: (-6.35,5.48) (6.35,5.48)
  round 1.3 hole 0.9: 1(3.57,8.02) 2(2.55,9.8) 3(1.53,8.02) 4(0.51,9.8) 5(-0.51,8.02) 6(-1.53,9.8) 7(-2.55,8.02) 8(-3.57,9.8)
  round 1.5 hole 0.9: 9(-6.86,14.62) 10(-4.57,14.62) 11(4.57,14.62) 12(6.86,14.62)
  round 2.2 hole 1.6: 13(-8.13,8.91) 14(8.13,8.91)
CON_SATA
  round 1.1 hole 0.74: 1(-3.81,1.5) 2(-2.54,0) 3(-1.27,0) 4(0,1.5) 5(1.27,0) 6(2.54,0) 7(3.81,1.5)
  round 1.85 hole 1.35: 8(-6.27,0) 9(6.56,-1)
CON_SD
  round 1.5 hole 1.5 unplated: (-12.1,5.5) (12.1,5.5)
  rect 0.8x2 smd: 1(-6.88,30) 2(-4.38,30) 3(-1.05,30) 4(0.62,30) 5(3.12,30) 6(5.62,30) 7(8.05,30) 8(9.75,30) 9(-9.38,30) 10(-2.71,30)
  rect 0.7x2 smd: 11(13.24,30)
  rect 1.8x2.4 smd: 12(-14.1,8.8)
  rect 1.7x2.4 smd: 13(13.25,7.6)
CON_SFP
  round 1.55 hole 1.55 unplated: (-4.8,35.4) (4.8,35.4)
  rect 0.5x2 smd: 1(-3.395,31.3) 2(-2.595,31.3) 3(-1.795,31.3) 4(-0.995,31.3) 5(-0.195,31.3) 6(0.605,31.3) 7(1.405,31.3) 8(2.205,31.3) 9(3.005,31.3) 10(3.805,31.3) 11(3.405,39.5) 12(2.605,39.5) 13(1.805,39.5) 14(1.005,39.5) 15(0.205,39.5) 16(-0.595,39.5) 17(-1.395,39.5) 18(-2.195,39.5) 19(-2.995,39.5) 20(-3.795,39.5)
CON_SFP_CAGE
  rect 2x2 hole 1.05: 1(-7.125,4.5) 2(1.45,4.5) 3(7.125,9.5) 4(-7.125,14.5) 5(7.125,19.5) 6(-7.125,24.5) 7(-1.45,24.5) 8(3.95,24.5) 9(7.125,29.5) 10(7.125,39.5)
  round 1.2 hole 0.95: 11(-7.125,27.3) 12(7.125,27.3) 13(-7.125,32) 14(7.125,32) 15(-7.125,37) 16(7.125,37) 18(-4.8,41.6) 19(0,41.6) 20(4.8,41.6)
  rect 2x2 hole 0.85: 17(-7.125,34.5)
CON_SW_60X60_2P2_34
  round 1.5 hole 1: 1(-2.25,2.45) 2(2.25,2.45)
  round 1.8 hole 1.3: 3(-3.5,4.95) 4(3.5,4.95)
CON_SWITCH_X8
  rect 1.27x0.76 smd: 1(-3.81,4.445) 2(-3.81,3.175) 3(-3.81,1.905) 4(-3.81,0.635) 5(-3.81,-0.635) 6(-3.81,-1.905) 7(-3.81,-3.175) 8(-3.81,-4.445) 9(3.81,-4.445) 10(3.81,-3.175) 11(3.81,-1.905) 12(3.81,-0.635) 13(3.81,0.635) 14(3.81,1.905) 15(3.81,3.175) 16(3.81,4.445)
CON_USB_A_2
  round 1.4 hole 0.9: 1(-3.5,15.61) 2(-1,15.61) 3(1,15.61) 4(3.5,15.61) 5(-3.5,12.99) 6(-1,12.99) 7(1,12.99) 8(3.5,12.99)
  round 3.3 hole 2.3: 9(-6.57,10.28) 10(6.57,10.28) 11(-6.57,15.96) 12(6.57,15.96)
CON_WAFER_P254_S_1X3
  round 1.5 hole 1: 1(-2.54,0) 2(0,0) 3(2.54,0)
CRY_32X25_4
  rect 1.4x1.2 smd: 1(-1.1,-0.85) 2(1.1,-0.85) 3(1.1,0.85) 4(-1.1,0.85)
DFN_P050_D040_B300_10_E240X165
  custom 0.07x0.07 smd: 1(-1.5,1) 2(-1.5,0.5) 3(-1.5,0) 4(-1.5,-0.5) 5(-1.5,-1) 6(1.5,-1) 7(1.5,-0.5) 8(1.5,0) 9(1.5,0.5) 10(1.5,1)
  custom 0.412x0.412 smd: 11(0,0)
FIDUCIAL
  round 1 smd: 1(0,0)
HDR_P254_HTST_2X8
  rect 5.08x1.27 smd: 1(-3.43,0) 2(3.43,0) 3(-3.43,-2.54) 4(3.43,-2.54) 5(-3.43,-5.08) 6(3.43,-5.08) 7(-3.43,-7.62) 8(3.43,-7.62) 9(-3.43,-10.16) 10(3.43,-10.16) 11(-3.43,-12.7) 12(3.43,-12.7) 13(-3.43,-15.24) 14(3.43,-15.24) 15(-3.43,-17.78) 16(3.43,-17.78)
HDR_P254_M_T_1X3
  rect 1.5x1.5 hole 1: 1(0,0)
  round 1.5 hole 1: 2(0,-2.54) 3(0,-5.08)
HDR_P254_M_T_2X5
  rect 1.5x1.5 hole 1: 1(-1.27,0)
  round 1.5 hole 1: 2(1.27,0) 3(-1.27,-2.54) 4(1.27,-2.54) 5(-1.27,-5.08) 6(1.27,-5.08) 7(-1.27,-7.62) 8(1.27,-7.62) 9(-1.27,-10.16) 10(1.27,-10.16)
HS_T1040
  round 3.7 hole 2.7: 1(-25.5,25.5) 2(25.5,25.5) 3(-25.5,-25.5) 4(25.5,-25.5)
IND_45X40
  custom 0.412x0.412 smd: 1(0,1.675) 2(0,-1.675)
IND_CM_2012
  rect 0.9x0.4 smd: 1(-0.85,-0.35) 2(0.85,-0.35) 3(0.85,0.35) 4(-0.85,0.35)
IND_FP1007
  rect 3x2.5 smd: 1(-3.85,0) 2(3.85,0)
IND_IHLP_2525
  rect 1.83x3.43 smd: 1(-2.77,0) 2(2.77,0)
IND_SWPA2520
  rect 0.85x2 smd: 1(-0.825,0) 2(0.825,0)
IND_SWRB07
  rect 1.5x2 smd: 1(-3.2,0) 2(3.2,0)
JMP_P254_T_1X2
  round 1.5 hole 1: 1(0,0) 2(0,-2.54)
LED_0603
  rect 0.9x0.9 smd: 1(-0.8,0) 2(0.8,0)
LED_PM_1S
  rect 1.5x3.5 smd: 1(1.27,5.25) 2(-1.27,5.25)
MAG_GST5009
  rect 0.6x1.35 smd: 1(-5.5,-4.675) 2(-4.5,-4.675) 3(-3.5,-4.675) 4(-2.5,-4.675) 5(-1.5,-4.675) 6(-0.5,-4.675) 7(0.5,-4.675) 8(1.5,-4.675) 9(2.5,-4.675) 10(3.5,-4.675) 11(4.5,-4.675) 12(5.5,-4.675) 13(5.5,4.675) 14(4.5,4.675) 15(3.5,4.675) 16(2.5,4.675) 17(1.5,4.675) 18(0.5,4.675) 19(-0.5,4.675) 20(-1.5,4.675) 21(-2.5,4.675) 22(-3.5,4.675) 23(-4.5,4.675) 24(-5.5,4.675)
MH_580S340P
  rect 5.8x5.8 hole 3.4: 1(0,0)
MH_900C400N_M
  round 4 hole 4 unplated: (0,0)
  round 1 hole 0.5: 1(0,3) 2(-2.121,2.121) 3(-3,0) 4(-2.121,-2.121) 5(0,-3) 6(2.121,-2.121) 7(3,0) 8(2.121,2.121)
MSOP_8
  rect 1.5x0.35 smd: 1(-2.2,0.975) 2(-2.2,0.325) 3(-2.2,-0.325) 4(-2.2,-0.975) 5(2.2,-0.975) 6(2.2,-0.325) 7(2.2,0.325) 8(2.2,0.975)
MSOP_8_E170
  rect 1.5x0.35 smd: 1(-2.2,0.975) 2(-2.2,0.325) 3(-2.2,-0.325) 4(-2.2,-0.975) 5(2.2,-0.975) 6(2.2,-0.325) 7(2.2,0.325) 8(2.2,0.975)
  rect 1.7x1.7 smd: 9(0,0)
MSOP_10
  rect 1.5x0.28 smd: 1(-2.2,1) 2(-2.2,0.5) 3(-2.2,0) 4(-2.2,-0.5) 5(-2.2,-1) 6(2.2,-1) 7(2.2,-0.5) 8(2.2,0) 9(2.2,0.5) 10(2.2,1)
NFM21
  rect 0.8x1.4 smd: 1(-1,0) 2(1,0)
  rect 0.7x0.7 smd: 3(0,0.625) 4(0,-0.625)
OSC_7X5_4
  rect 1.8x2 smd: 1(-2.54,-2.1) 2(2.54,-2.1) 3(2.54,2.1) 4(-2.54,2.1)
OSC_32X25_4
  rect 1.4x1.2 smd: 1(-1.1,-0.85) 2(1.1,-0.85) 3(1.1,0.85) 4(-1.1,0.85)
PTC_SM013
  rect 2.41x2.29 smd: 1(-1.97,0.57) 2(1.97,-0.57)
QFN_IR3550
  oval 0.65x0.25 smd: 1(-3,2.275) 2(-3,1.775) 3(-3,1.275) 4(-3,0.775) 5(-3,0.275) 6(-3,-2.375)
  custom 0.219x0.219 smd: 7(0,-3)
  custom 0.36x0.36 smd: 16(0,-1.5)
  custom 0.408x0.408 smd: 18(0,1.19)
  oval 0.25x0.65 smd: 20(2.425,3) 21(1.925,3) 22(1.425,3) 23(0.925,3) 24(0.425,3) 25(-0.075,3) 26(-0.575,3) 27(-1.075,3) 28(-1.575,3) 29(-2.075,3) 30(-2.575,3)
  rect 1.63x1.95 smd: 31(-1.485,1.325)
  rect 0.55x0.34 smd: 32(-2.055,-0.53)
